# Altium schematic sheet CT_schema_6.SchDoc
size 274 x 160 mm
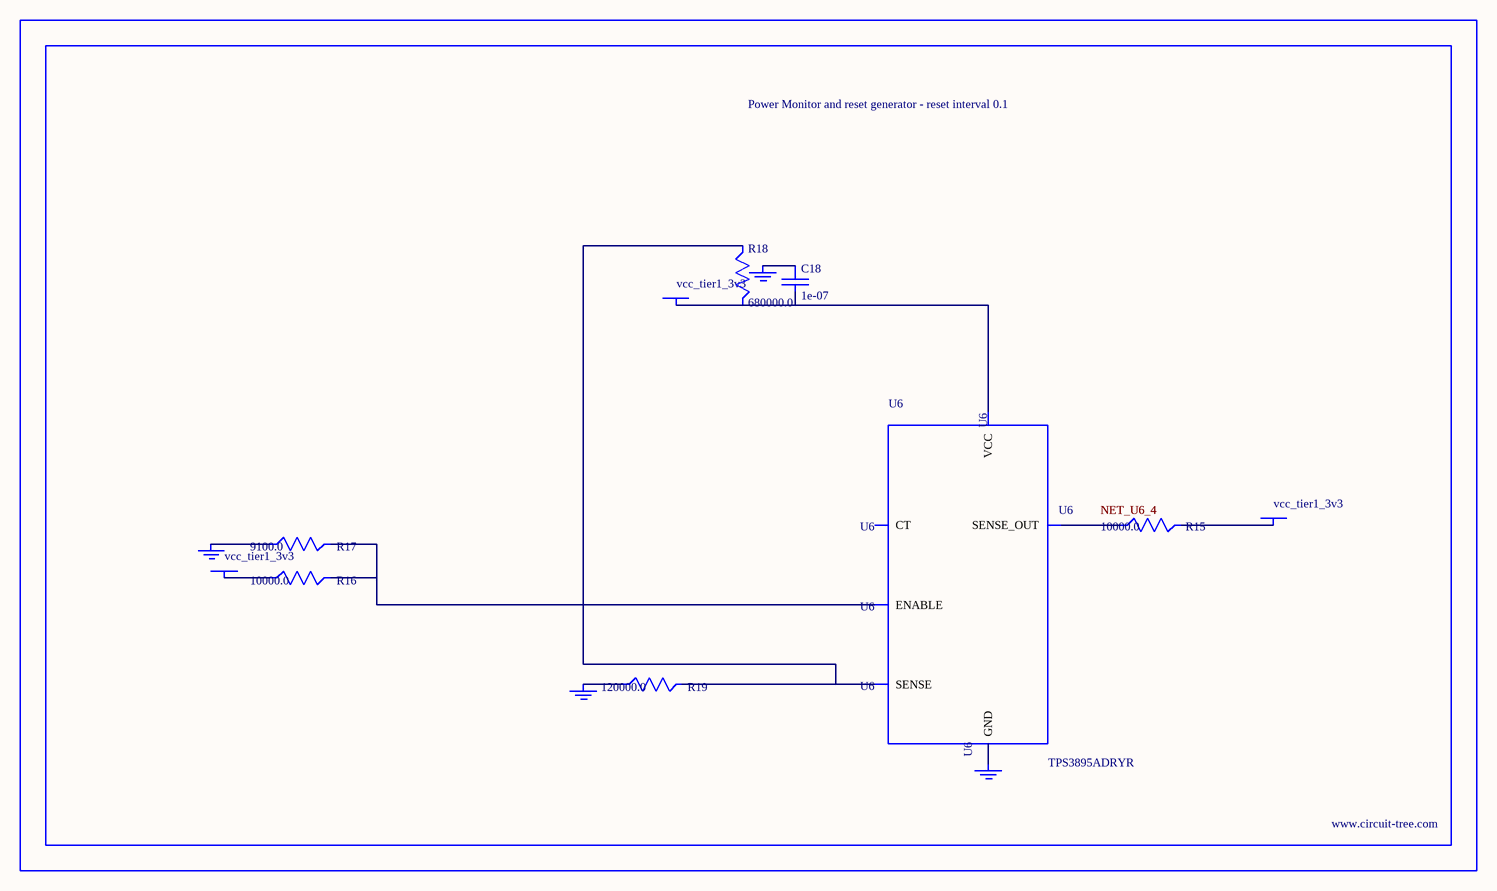
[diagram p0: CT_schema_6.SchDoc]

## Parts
BORDER5  (no value)
C18  1e-07  [C0402]
GND_INSTANCE_5_0  (no value)
GND_INSTANCE_5_1  (no value)
GND_INSTANCE_5_2  (no value)
GND_INSTANCE_5_3  (no value)
POWER_INSTANCE_5_0  vcc_tier1_3v3
POWER_INSTANCE_5_1  vcc_tier1_3v3
POWER_INSTANCE_5_2  vcc_tier1_3v3
R15  10000.0  [R0603]
R16  10000.0  [R0603]
R17  9100.0  [R0603]
R18  680000.0  [R0603]
R19  120000.0  [R0603]
U6  TPS3895ADRYR  [SON-6]

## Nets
NetC18_1: C18.1 GND_INSTANCE_5_2.0(GND)
NetC18_2: C18.2 POWER_INSTANCE_5_2.0(PWR) R18.2 U6.6(VCC)
NetGND_INSTANCE_5_0_0: GND_INSTANCE_5_0.0(GND) R17.1
NetGND_INSTANCE_5_1_0: GND_INSTANCE_5_1.0(GND) R19.1
NetGND_INSTANCE_5_3_0: GND_INSTANCE_5_3.0(GND) U6.2(GND)
NetPOWER_INSTANCE_5_0_0: POWER_INSTANCE_5_0.0(PWR) R16.1
NetPOWER_INSTANCE_5_1_0: POWER_INSTANCE_5_1.0(PWR) R15.2
NetR15_1: R15.1 U6.4(SENSE_OUT)
NetR16_2: R16.2 R17.2 U6.1(ENABLE)
NetR18_1: R18.1 R19.2 U6.3(SENSE)

Not connected (* = marked no-connect by the designer): U6 5(CT)

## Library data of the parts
BORDER5 = BORDER_PAGE5
C18 = C0402C104K3RACTU
GND_INSTANCE_5_0-GND_INSTANCE_5_3 = GND
POWER_INSTANCE_5_0-POWER_INSTANCE_5_2 = PWR
R15 R16 = RC0603JR-0710KL
R17 = RC0603JR-079K1L
R18 = RC0603JR-07680KL
R19 = RC0603JR-07120KL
